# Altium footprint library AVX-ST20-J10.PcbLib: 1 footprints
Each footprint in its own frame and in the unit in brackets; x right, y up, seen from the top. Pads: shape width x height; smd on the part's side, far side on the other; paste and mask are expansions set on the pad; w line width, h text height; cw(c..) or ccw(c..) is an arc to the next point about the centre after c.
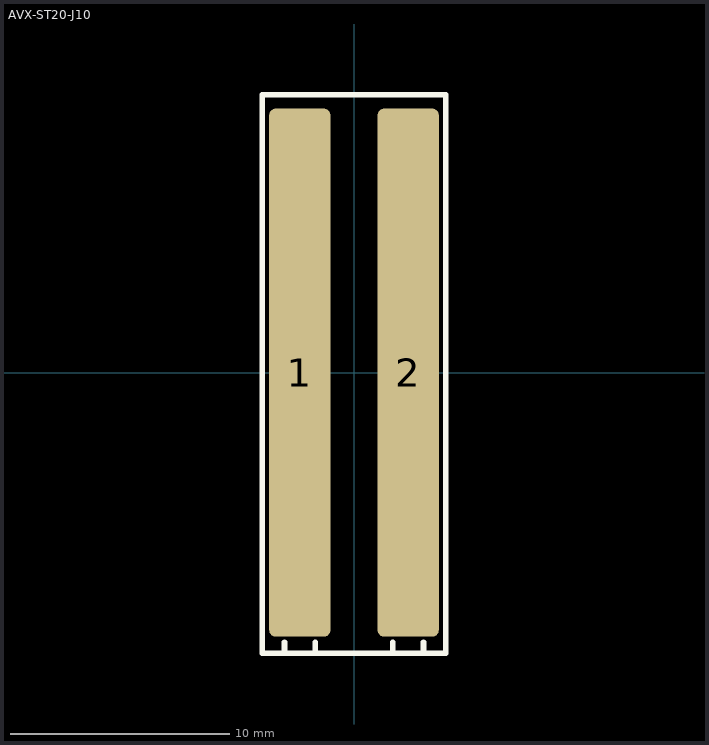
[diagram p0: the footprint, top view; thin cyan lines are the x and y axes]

## AVX-ST20-J10 [mil]
pads (2):
  rrect20% 110x950 smd: 1(-97.5,0) 2(97.5,0)
Top Overlay:
  lines w10: -125,-505 -125,-485 ; -70,-505 -70,-485 ; 70,-505 70,-485 ; 125,-505 125,-485 ; -165,-505 165,-505 165,500 -165,500 -165,-505
3D body: height 285, standoff 0, extent -165,-505 165,500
